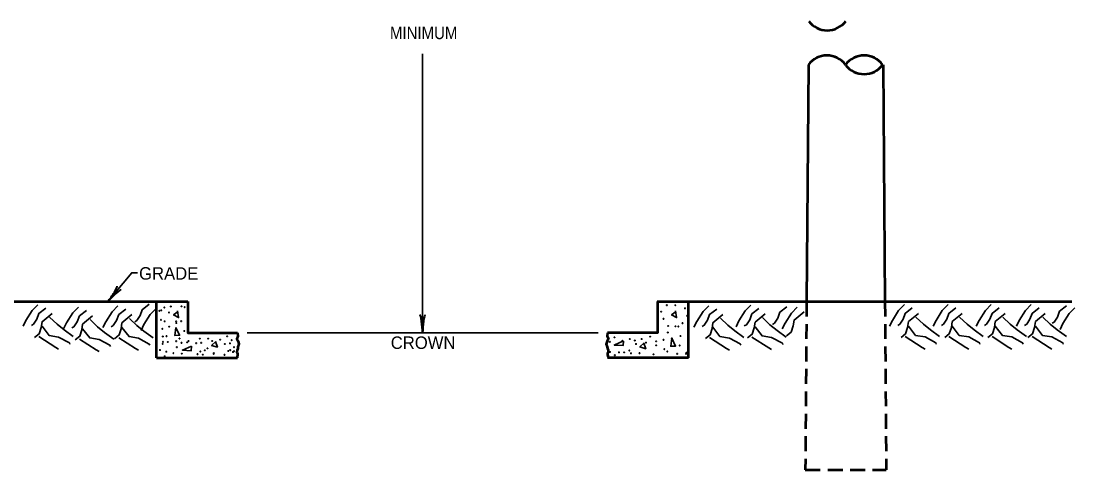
# Model space of a CAD drawing. Extents: x -368 to 312, y -34 to 406.
# Drawn here: x -151.6 to 17.6, y 192.7 to 264.7 of the extents above; entities that cross this region are included whole.
import ezdxf
from ezdxf.enums import TextEntityAlignment as Align

# ---------------------------------------------------------------- set-up
doc = ezdxf.new("R2010")
doc.units = 0
doc.header["$LTSCALE"] = 0.8
doc.linetypes.add('MEDIUM_DASHED', pattern=[4.5, 3, -1.5])
doc.layers.add('1', color=7, linetype='Continuous', lineweight=53)

msp = doc.modelspace()

# ---------------------------------------------------------------- linework, layer by layer
at = {"layer": '1', "lineweight": 35}
for p, q in [((-87.1562, 214.6552), (-87.1562, 259.3816)), ((-115.35, 214.6552), (-58.9385, 214.6552))]:
    msp.add_line(p, q, dxfattribs=at)
at = {"layer": '1'}
for p, q in [((-25.1663, 257.6552), (-25.4587, 219.6552)), ((-13.1663, 257.6552), (-12.874, 219.6552)), ((-188.4587, 219.6552), (-124.874, 219.6552)), ((-129.874, 210.6552), (-129.874, 219.6552)), ((-49.4587, 219.6552), (17.126, 219.6552)), ((-44.4385, 210.6552), (-44.4385, 219.6552)), ((-129.874, 210.6552), (-116.874, 210.6552)), ((-44.4385, 210.6552), (-57.4385, 210.6552))]:
    msp.add_line(p, q, dxfattribs=at)
at = {"layer": '1', "linetype": 'MEDIUM_DASHED'}
for p, q in [((-25.4587, 219.6552), (-25.6663, 192.6552)), ((-12.874, 219.6552), (-12.6663, 192.6552)), ((-25.6663, 192.6552), (-12.6663, 192.6552))]:
    msp.add_line(p, q, dxfattribs=at)
at = {"layer": '1', "lineweight": 35}
for points in [[(-137.7483, 219.6285), (-133.8617, 224.2742), (-132.9394, 224.2742)], [(-148.9305, 219.1572), (-149.8612, 218.2262), (-150.8583, 216.6302), (-151.3237, 215.6993)], [(-147.6674, 218.6252), (-148.7976, 217.7608), (-149.1299, 216.8297), (-149.6617, 216.0318), (-149.9941, 215.8323)], [(-142.4159, 218.7582), (-143.3466, 217.8272), (-144.3438, 216.2312), (-144.8091, 215.3003)], [(-136.1006, 218.9577), (-137.0312, 218.0267), (-138.0284, 216.4307), (-138.4938, 215.4998)], [(-134.8375, 218.4257), (-135.9677, 217.5613), (-136.3, 216.6302), (-136.8318, 215.8323), (-137.1642, 215.6328)], [(-131.0482, 219.2237), (-132.1783, 218.3593), (-132.5107, 217.4282), (-133.0425, 216.6303), (-133.3748, 216.4308)], [(-129.9847, 218.4922), (-130.9153, 217.5613), (-131.9125, 215.9652), (-132.3778, 215.0343)], [(-41.1706, 218.9961), (-42.1013, 218.0652), (-43.0984, 216.4692), (-43.5637, 215.5383)], [(-39.9075, 218.4642), (-41.0377, 217.5997), (-41.37, 216.6687), (-41.9018, 215.8707), (-42.2342, 215.6712)], [(-34.404, 219.0797), (-35.3347, 218.1488), (-36.3318, 216.5528), (-36.7972, 215.6218)], [(-33.1409, 218.5477), (-34.2711, 217.6832), (-34.6034, 216.7523), (-35.1352, 215.9543), (-35.4676, 215.7548)], [(-28.6298, 218.7985), (-29.76, 217.934), (-30.0923, 217.003), (-30.6242, 216.2051), (-30.9565, 216.0056)], [(-26.9692, 218.7454), (-27.8998, 217.8145), (-28.897, 216.2185), (-29.3623, 215.2876)], [(-9.7604, 219.1633), (-10.6911, 218.2323), (-11.6883, 216.6363), (-12.1536, 215.7054)], [(-8.4973, 218.6313), (-9.6275, 217.7668), (-9.9598, 216.8358), (-10.4917, 216.0379), (-10.824, 215.8384)], [(-2.7432, 219.1633), (-3.6738, 218.2323), (-4.671, 216.6363), (-5.1363, 215.7054)], [(-1.4801, 218.6313), (-2.6102, 217.7668), (-2.9426, 216.8358), (-3.4744, 216.0379), (-3.8068, 215.8384)], [(4.1905, 219.1633), (3.2598, 218.2324), (2.2627, 216.6364), (1.7973, 215.7055)], [(5.4536, 218.6314), (4.3234, 217.7669), (3.9911, 216.8359), (3.4592, 216.038), (3.1269, 215.8385)], [(10.623, 219.1633), (9.6923, 218.2324), (8.6952, 216.6364), (8.2298, 215.7055)], [(11.8861, 218.6314), (10.7559, 217.7669), (10.4236, 216.8359), (9.8918, 216.038), (9.5594, 215.8385)], [(16.3136, 218.9657), (15.1834, 218.1012), (14.8511, 217.1702), (14.3193, 216.3723), (13.9869, 216.1728)], [(17.6402, 218.6619), (16.7095, 217.731), (15.7123, 216.135), (15.247, 215.2041)], [(-146.6703, 217.7608), (-148.2657, 216.4307), (-148.3987, 215.4998), (-148.7311, 214.5023), (-149.4623, 213.9038)], [(-147.0692, 217.1623), (-145.8726, 216.0318), (-144.7425, 215.1008), (-143.28, 214.0368)], [(-141.1528, 218.2262), (-142.283, 217.3618), (-142.6153, 216.4307), (-143.1472, 215.6328), (-143.4795, 215.4333)], [(-140.1557, 217.3618), (-141.7512, 216.0317), (-141.8841, 215.1008), (-142.2165, 214.1033), (-142.9477, 213.5048)], [(-140.5546, 216.7632), (-139.358, 215.6328), (-138.2279, 214.7018), (-136.7654, 213.6378)], [(-133.8404, 217.5613), (-135.4358, 216.2312), (-135.5687, 215.3003), (-135.9012, 214.3028), (-136.6324, 213.7043)], [(-134.2392, 216.9627), (-133.0427, 215.8323), (-131.9126, 214.9013), (-130.4501, 213.8373)], [(-126.4155, 218.0844), (-127.1479, 217.5286), (-126.3397, 217.0991), (-126.5165, 218.1854)], [(-46.4103, 218.0844), (-47.1427, 217.5286), (-46.3346, 217.0991), (-46.5113, 218.1854)], [(-38.9104, 217.5997), (-40.5058, 216.2697), (-40.6388, 215.3388), (-40.9712, 214.3413), (-41.7024, 213.7428)], [(-39.3092, 217.0012), (-38.1127, 215.8707), (-36.9826, 214.9398), (-35.5201, 213.8757)], [(-32.1438, 217.6832), (-33.7392, 216.3533), (-33.8722, 215.4223), (-34.2046, 214.4248), (-34.9358, 213.8263)], [(-32.5427, 217.0847), (-31.3461, 215.9543), (-30.216, 215.0233), (-28.7535, 213.9593)], [(-25.8785, 218.0175), (-27.4739, 216.6875), (-27.6068, 215.7566), (-27.9392, 214.7591), (-28.6705, 214.1606)], [(-7.5002, 217.7668), (-9.0957, 216.4368), (-9.2286, 215.5059), (-9.561, 214.5084), (-10.2922, 213.9099)], [(-7.8991, 217.1683), (-6.7025, 216.0379), (-5.5724, 215.1069), (-4.1099, 214.0429)], [(-0.483, 217.7668), (-2.0784, 216.4368), (-2.2113, 215.5059), (-2.5437, 214.5084), (-3.275, 213.9099)], [(-0.8818, 217.1683), (0.3147, 216.0379), (1.4448, 215.1069), (2.9073, 214.0429)], [(6.4507, 217.7669), (4.8552, 216.4369), (4.7223, 215.506), (4.3899, 214.5085), (3.6587, 213.91)], [(6.0518, 217.1684), (7.2484, 216.038), (8.3785, 215.107), (9.841, 214.043)], [(12.8832, 217.7669), (11.2877, 216.4369), (11.1548, 215.506), (10.8224, 214.5085), (10.0912, 213.91)], [(12.4843, 217.1684), (13.6809, 216.038), (14.811, 215.107), (16.2735, 214.043)], [(-148.2657, 215.6993), (-147.1357, 214.2363), (-145.6067, 213.9703), (-143.8783, 213.0394), (-143.8118, 212.8399)], [(-141.7512, 215.3003), (-140.6211, 213.8373), (-139.0921, 213.5713), (-137.3637, 212.6404), (-137.2972, 212.4409)], [(-135.4358, 215.4998), (-134.3057, 214.0368), (-132.7767, 213.7708), (-131.0483, 212.8399), (-130.9819, 212.6404)], [(-40.5058, 215.5383), (-39.3757, 214.0752), (-37.8468, 213.8092), (-36.1183, 212.8783), (-36.0519, 212.6788)], [(-33.7392, 215.6218), (-32.6092, 214.1588), (-31.0802, 213.8928), (-29.3517, 212.9619), (-29.2853, 212.7624)], [(-9.0957, 215.7054), (-7.9656, 214.2424), (-6.4366, 213.9764), (-4.7082, 213.0455), (-4.6418, 212.846)], [(-2.0784, 215.7054), (-0.9483, 214.2424), (0.5807, 213.9764), (2.3091, 213.0455), (2.3755, 212.846)], [(4.8552, 215.7055), (5.9853, 214.2425), (7.5143, 213.9765), (9.2427, 213.0456), (9.3092, 212.8461)], [(11.2877, 215.7055), (12.4178, 214.2425), (13.9468, 213.9765), (15.6753, 213.0456), (15.7417, 212.8461)], [(-148.7976, 214.0368), (-146.072, 212.3079), (-145.6067, 212.0419)], [(-142.283, 213.6378), (-139.5574, 211.9089), (-139.0921, 211.6429)], [(-135.9677, 213.8373), (-133.2421, 212.1084), (-132.7767, 211.8424)], [(-54.862, 213.3437), (-56.3522, 212.6867), (-54.9378, 212.5857), (-54.862, 213.3184)], [(-41.0377, 213.8757), (-38.3121, 212.1468), (-37.8468, 211.8808)], [(-34.2711, 213.9593), (-31.5455, 212.2304), (-31.0802, 211.9644)], [(-9.6275, 214.0429), (-6.9019, 212.314), (-6.4366, 212.048)], [(-2.6102, 214.0429), (0.1153, 212.314), (0.5807, 212.048)], [(4.3234, 214.043), (7.049, 212.3141), (7.5143, 212.0481)], [(10.7559, 214.043), (13.4815, 212.3141), (13.9468, 212.0481)], [(-124.2434, 212.5262), (-125.7336, 211.8692), (-124.3192, 211.7682), (-124.2434, 212.5009)], [(-120.3792, 213.2588), (-121.0358, 212.6273), (-120.1014, 212.3493), (-120.4297, 213.2336)], [(-51.5698, 213.0136), (-52.2265, 212.382), (-51.2921, 212.1041), (-51.6204, 212.9883)]]:
    msp.add_lwpolyline(points, dxfattribs=at)
at = {"layer": '1'}
for points in [[(-124.874, 219.6552), (-124.874, 214.6552), (-116.874, 214.6552)], [(-49.4385, 219.6552), (-49.4385, 214.6552), (-57.4385, 214.6552)], [(-116.874, 214.6552), (-116.8048, 214.1197), (-117.0087, 213.6847), (-116.7912, 213.3041), (-116.6689, 212.8419), (-116.8048, 212.407), (-116.8456, 212.1351), (-116.9543, 211.8497), (-116.9815, 211.5506), (-116.8863, 211.3467), (-116.8727, 211.0884), (-116.9543, 210.7214), (-116.874, 210.6552)], [(-57.4385, 214.6552), (-57.5077, 214.1197), (-57.3038, 213.6847), (-57.5212, 213.3041), (-57.6436, 212.8419), (-57.5077, 212.407), (-57.4669, 212.1351), (-57.3582, 211.8497), (-57.331, 211.5506), (-57.4262, 211.3467), (-57.4397, 211.0884), (-57.3582, 210.7214), (-57.4385, 210.6552)]]:
    msp.add_lwpolyline(points, dxfattribs=at)
at = {"layer": '1', "lineweight": 35}
for points in [[(-126.7943, 215.5074), (-126.9712, 214.2189), (-126.1882, 214.2442)], [(-47.1161, 213.7908), (-47.2929, 212.5023), (-46.5099, 212.5275)]]:
    msp.add_lwpolyline(points, close=True, dxfattribs=at)
for centre in [(-128.6381, 218.7159), (-127.5772, 218.8675), (-125.8851, 218.8928), (-125.3547, 218.7665), (-47.9046, 219.0935), (-46.556, 219.0694), (-44.9907, 218.5876), (-129.4462, 218.1854), (-129.1684, 216.72), (-129.1179, 218.2612), (-127.8803, 217.9075), (-48.8197, 218.0336), (-48.4584, 216.9014), (-44.6536, 217.3832), (-128.9664, 215.2799), (-128.5875, 216.4927), (-127.8551, 215.6337), (-126.7438, 216.4927), (-126.6933, 216.2147), (-125.9356, 216.5179), (-125.4305, 214.9515), (-47.7119, 215.7451), (-46.5319, 215.6969), (-46.0743, 215.6728), (-45.4001, 216.2028), (-128.8653, 214.0673), (-128.2845, 214.1178), (-126.7438, 213.3093), (-126.1882, 213.7388), (-124.7486, 213.3346), (-122.9301, 213.7135), (-121.5915, 213.7135), (-120.9601, 213.3346), (-119.672, 213.5367), (-118.5355, 214.0925), (-117.8283, 213.4609), (-56.3089, 213.9143), (-55.0567, 213.3602), (-53.8526, 213.6493), (-53.0579, 213.4085), (-51.9502, 213.6493), (-50.6017, 214.0348), (-49.6143, 213.288), (-48.4584, 213.5289), (-47.7601, 214.7092), (-47.1098, 213.7698), (-45.7132, 214.1312), (-129.3275, 211.8833), (-128.8906, 212.8798), (-128.8401, 213.2082), (-128.3098, 211.6166), (-128.0572, 213.183), (-126.6175, 212.3492), (-125.8851, 213.0314), (-124.9758, 213.1072), (-123.511, 212.9808), (-122.8543, 211.6418), (-122.7027, 213.0314), (-122.1219, 211.8439), (-121.6925, 212.1471), (-118.9143, 212.8545), (-118.3587, 211.7429), (-118.0808, 212.9556), (-118.0556, 211.8945), (-118.0303, 211.8692), (-117.601, 211.566), (-117.4494, 212.3492), (-117.4494, 211.6923), (-57.0795, 213.1917), (-57.0313, 211.5777), (-53.9248, 211.8186), (-52.8652, 212.8544), (-51.2518, 213.0712), (-49.6143, 212.6376), (-48.3139, 212.0354), (-47.8323, 211.65), (-45.8577, 212.6135), (-128.5694, 210.8802), (-127.1732, 211.3892), (-125.8093, 211.3134), (-123.3089, 211.2123), (-122.4502, 211.1365), (-120.7075, 211.2628), (-120.6822, 211.3892), (-118.9648, 211.1112), (-56.2608, 211.0718), (-55.5864, 211.5054), (-54.7677, 211.5054), (-53.6599, 211.3609), (-52.3114, 211.385), (-50.0478, 211.1923), (-46.2429, 211.2646), (-44.8462, 211.2646), (-44.7499, 211.4572)]:
    msp.add_circle(centre, 0.0565, dxfattribs=at)
at = {"layer": '1'}
for centre, start, end in [((-22.1394, 266.8687), 216.66818, 323.33182), ((-22.1932, 255.4417), 36.66818, 143.33182), ((-16.2272, 255.4417), 36.66818, 143.33182), ((-16.2272, 259.8522), 216.66818, 323.33182)]:
    msp.add_arc(centre, 3.7066, start, end, dxfattribs=at)
at = {"layer": '1', "lineweight": 40}
for centre, major_axis, ratio, start_param, end_param in [((-137.2601, 220.6427), (-1.0261, -1.4698), 0.122415, 0.89635335, 3.14159265), ((-136.8671, 220.3521), (-1.2618, -1.2345), 0.07063, 3.14071475, 5.41810995), ((-87.4325, 215.7464), (0.1562, -1.7857), 0.122415, 0.89635335, 3.14159265), ((-86.9446, 215.7757), (-0.1757, -1.7565), 0.07063, 3.14071475, 5.41810995)]:
    msp.add_ellipse(centre, major_axis=major_axis, ratio=ratio, start_param=start_param, end_param=end_param, dxfattribs=at)

# ---------------------------------------------------------------- texts
at = {"layer": '1', "width": 0.9}
msp.add_text('MINIMUM', height=2, dxfattribs=at).set_placement((-86.9737, 261.7641), align=Align.CENTER)
at = {"layer": '1'}
for s, p in [('GRADE', (-127.9328, 223.1753)), ('CROWN', (-87.0622, 212.0612))]:
    msp.add_text(s, height=2, dxfattribs=at).set_placement(p, align=Align.CENTER)

doc.saveas('drawing.dxf')
